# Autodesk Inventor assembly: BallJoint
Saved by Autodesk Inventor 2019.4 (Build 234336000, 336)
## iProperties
Created: 2020-02
Part Number: BallJoint
Document SubType Name: Assembly
Designer: Administrator
Title: BallJoint v14
Author: Administrator
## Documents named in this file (3)
- c:\worker\convert-fusion-r01\tmp\job-1\5\output\files\e4333473-a38b-4431-9958-ad24a2f67704\BallJoint v14_4.iam
- c:\worker\convert-fusion-r01\tmp\job-1\5\output\files\e4333473-a38b-4431-9958-ad24a2f67704\Component1_1.ipt
- c:\worker\convert-fusion-r01\tmp\job-1\5\output\files\e4333473-a38b-4431-9958-ad24a2f67704\Component2_1.ipt
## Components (2 placed, 2 different names)
1. Component1:1
2. Component2:1
